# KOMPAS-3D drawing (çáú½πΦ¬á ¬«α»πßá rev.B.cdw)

Views: Вид 1, Спереди
Referenced files in E:\: Заглушка корпуса.m3d, Чертеж Заглушка корпуса.cdw
Referenced files in D:\_Downloads\: Заглушка корпуса.m3d
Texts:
  Im2
  Заглушка корпуса
Dimensions and other numbers on the sheet: 15; 34,5; 12,5; 27; 32,5; 36; 27,5; 16,5; 4; 8; 33,5; 25; 13; 10,5; 19,5; 28; 1,75; 3,1; 7; 9; 164; 57; 1:1; 0,06; 1; 0; 2; 3; 5; 6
